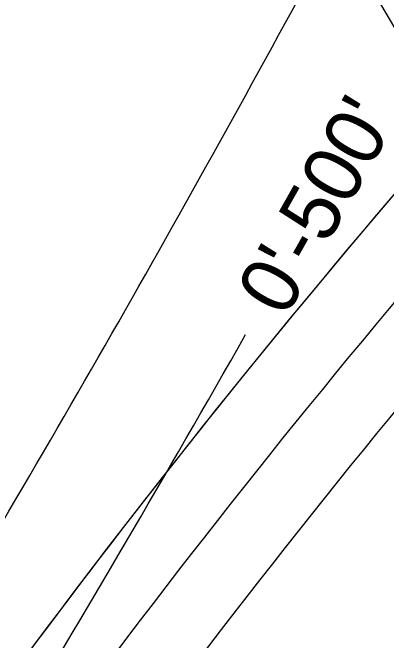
# Model space of a CAD drawing. Extents: x 14097936 to 14128734, y 8632000 to 8683104.
# Drawn here: x 14119491.1 to 14119555.3, y 8669580.6 to 8669688.3 of the extents above; entities that cross this region are included whole.
import ezdxf

# ---------------------------------------------------------------- set-up
doc = ezdxf.new("R2010")
doc.units = 0
for name, color, linetype in [('dsnPaintExistingChannelizingLaneWhite', 7, 'Continuous'), ('dsnPaintExistingDoubleCenterYellow', 7, 'Continuous'), ('dsnPavementRmvl', 7, 'Continuous'), ('dsnShadingPaved', 7, 'Continuous'), ('dsnStdLabel', 7, 'Continuous'), ('dsnStgShadingPropPav', 7, 'Continuous'), ('dsnTextOverlapEven', 7, 'Continuous')]:
    doc.layers.add(name, color=color, linetype=linetype)

msp = doc.modelspace()

# ---------------------------------------------------------------- linework, layer by layer
at = {"layer": 'dsnPaintExistingChannelizingLaneWhite'}
for radius in [1512, 1488]:
    msp.add_arc((14120706.26, 8668675.12), radius, 138.43496, 147.24256, dxfattribs=at)
at = {"layer": 'dsnPaintExistingDoubleCenterYellow'}
msp.add_arc((14120706.26, 8668675.12), 1500, 138.43496, 147.24256, dxfattribs=at)
at = {"layer": 'dsnPavementRmvl'}
for radius, start in [(1512, 137.73115), (1488, 138.43496)]:
    msp.add_arc((14120706.26, 8668675.12), radius, start, 147.24256, dxfattribs=at)
at = {"layer": 'dsnShadingPaved'}
for centre, radius, start, end in [((14117116.91, 8670980.36), 2830.2, 327.25475, 332.18395), ((14117116.91, 8670980.36), 2842.2, 327.24958, 332.18395), ((14117116.91, 8670980.36), 2842.2, 327.25434, 332.18395), ((14117117.1, 8670980.68), 2854.19, 327.24165, 332.17585), ((14117116.91, 8670980.36), 2854.2, 327.24958, 332.18395), ((14117117.1, 8670980.68), 2878.19, 327.24148, 332.17585)]:
    msp.add_arc(centre, radius, start, end, dxfattribs=at)
at = {"layer": 'dsnStdLabel'}
for radius, start, end in [(2903.66, 328.79417, 331.75546), (2923.66, 328.83376, 330.44861)]:
    msp.add_arc((14116987.75, 8671075.02), radius, start, end, dxfattribs=at)
at = {"layer": 'dsnStgShadingPropPav'}
for radius, start in [(1512, 137.73115), (1488, 138.43496)]:
    msp.add_arc((14120706.26, 8668675.12), radius, start, 147.24256, dxfattribs=at)
at = {"layer": 'dsnTextOverlapEven'}
msp.add_lwpolyline([(14119566.02, 8669784.57), (14119535.13, 8669722.09), (14119593.5, 8669623.33)], dxfattribs=at)

# ---------------------------------------------------------------- texts
at = {"layer": 'dsnStdLabel'}
msp.add_text("0'-500'", height=10, rotation=60.6002, dxfattribs=at).set_placement((14119537.9, 8669635.73))

doc.saveas('drawing.dxf')
